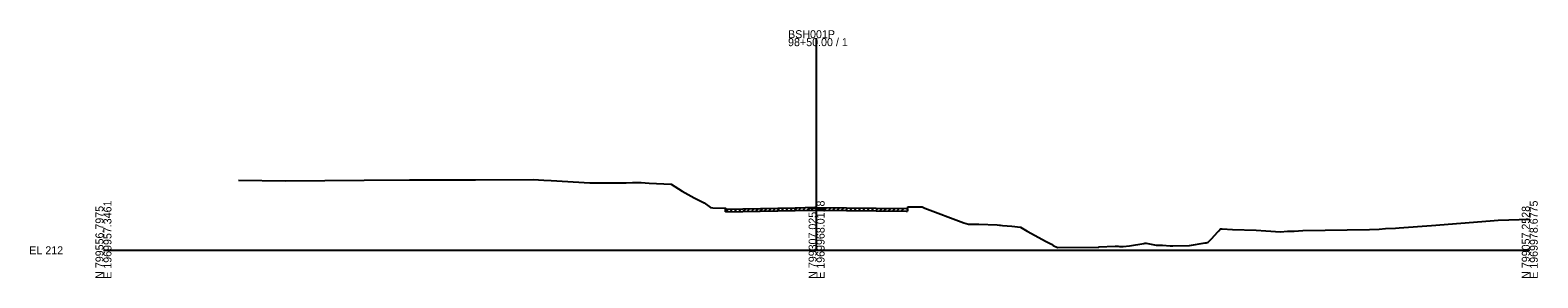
# Model space of a CAD drawing. Extents: x 1979833 to 1982361, y 790388 to 810009.
# Drawn here: x 1981583 to 1982111, y 799888 to 799975 of the extents above; entities that cross this region are included whole.
import ezdxf

# ---------------------------------------------------------------- set-up
doc = ezdxf.new("R2010")
doc.units = 0
for name, color, linetype in [('Default', 7, 'Continuous'), ('RD_GPK_XS_Cell', 7, 'Continuous'), ('RD_XS_ExGround', 7, 'Continuous'), ('RD_XS_ExPaveRet', 7, 'Continuous')]:
    doc.layers.add(name, color=color, linetype=linetype)

msp = doc.modelspace()

# ---------------------------------------------------------------- linework, layer by layer
at = {"layer": 'RD_GPK_XS_Cell'}
for p, q in [((1981858.57, 799897.73), (1981858.57, 799972.27)), ((1981608.57, 799897.73), (1981858.57, 799897.73)), ((1981858.57, 799897.73), (1982108.57, 799897.73))]:
    msp.add_line(p, q, dxfattribs=at)
at = {"layer": 'RD_XS_ExGround'}
msp.add_lwpolyline([(1981655.95, 799922.33), (1981672.36, 799922.18), (1981699.97, 799922.41), (1981715.87, 799922.5), (1981734.9, 799922.49), (1981739.05, 799922.5), (1981759.16, 799922.58), (1981763, 799922.37), (1981765.52, 799922.23), (1981779.02, 799921.48), (1981780.91, 799921.41), (1981791.78, 799921.49), (1981794.04, 799921.51), (1981797.08, 799921.54), (1981799.82, 799921.31), (1981807.58, 799920.92), (1981811.42, 799918.54), (1981815.6, 799916.15), (1981819.2, 799914.38), (1981821.37, 799912.73), (1981822.16, 799912.71), (1981826.59, 799912.51), (1981826.69, 799912.21), (1981851.11, 799912.7), (1981857.92, 799912.84), (1981858.57, 799912.83), (1981889.93, 799912.47), (1981890.49, 799912.47), (1981890.59, 799912.97), (1981895.57, 799912.97), (1981896.51, 799912.57), (1981910.17, 799907.4), (1981911.81, 799906.97), (1981915.43, 799906.89), (1981921.92, 799906.65), (1981922.67, 799906.57), (1981923.04, 799906.54), (1981923.74, 799906.48), (1981927.05, 799906.18), (1981930.06, 799905.83), (1981932.37, 799904.52), (1981939.1, 799900.89), (1981940.87, 799899.84), (1981941.5, 799899.44), (1981943.06, 799898.78), (1981957.51, 799898.89), (1981957.54, 799898.91), (1981963.23, 799899.16), (1981963.8, 799899.2), (1981964.33, 799899.14), (1981964.78, 799899.06), (1981965.31, 799899.05), (1981966.09, 799899.09), (1981968.23, 799899.27), (1981973.23, 799900.16), (1981973.67, 799900.25), (1981974.05, 799900.19), (1981976.97, 799899.65), (1981977.58, 799899.56), (1981978.83, 799899.55), (1981979.88, 799899.56), (1981982.52, 799899.27), (1981983.45, 799899.34), (1981989.24, 799899.4), (1981994.84, 799900.34), (1981995.17, 799900.38), (1981995.83, 799900.58), (1981996.97, 799901.74), (1981999.18, 799904.26), (1981999.58, 799904.56), (1982000.12, 799905.29), (1982000.7, 799905.25), (1982004.4, 799905.08), (1982012.64, 799904.78), (1982016.06, 799904.54), (1982021.18, 799904.25), (1982023.69, 799904.46), (1982024.6, 799904.42), (1982026.02, 799904.51), (1982029.06, 799904.66), (1982052.34, 799905.06), (1982055.8, 799905.22), (1982058.03, 799905.38), (1982061.54, 799905.52), (1982062.8, 799905.58), (1982074.09, 799906.46), (1982094.71, 799908.14), (1982097.44, 799908.3), (1982108.57, 799908.73)], dxfattribs=at)
at = {"layer": 'RD_XS_ExPaveRet'}
for p, q in [((1981826.69, 799911.21), (1981827.71, 799912.23)), ((1981826.69, 799911.21), (1981826.69, 799912.21)), ((1981826.69, 799911.21), (1981851.11, 799911.7)), ((1981828.19, 799911.24), (1981829.21, 799912.26)), ((1981829.69, 799911.27), (1981830.71, 799912.29)), ((1981831.19, 799911.3), (1981832.21, 799912.32)), ((1981832.69, 799911.33), (1981833.71, 799912.35)), ((1981834.19, 799911.36), (1981835.21, 799912.38)), ((1981835.69, 799911.39), (1981836.71, 799912.41)), ((1981837.19, 799911.42), (1981838.21, 799912.44)), ((1981838.69, 799911.45), (1981839.71, 799912.47)), ((1981840.19, 799911.48), (1981841.21, 799912.5)), ((1981841.69, 799911.51), (1981842.71, 799912.53)), ((1981843.19, 799911.54), (1981844.21, 799912.56)), ((1981844.69, 799911.57), (1981845.71, 799912.59)), ((1981846.19, 799911.6), (1981847.21, 799912.62)), ((1981847.69, 799911.63), (1981848.71, 799912.66)), ((1981849.19, 799911.66), (1981850.21, 799912.69)), ((1981850.69, 799911.69), (1981851.71, 799912.71)), ((1981851.11, 799911.7), (1981857.92, 799911.84)), ((1981852.19, 799911.72), (1981853.21, 799912.74)), ((1981853.69, 799911.75), (1981854.71, 799912.77)), ((1981855.19, 799911.78), (1981856.21, 799912.8)), ((1981856.69, 799911.81), (1981857.71, 799912.83)), ((1981857.92, 799911.84), (1981858.57, 799911.83)), ((1981858.19, 799911.83), (1981859.18, 799912.82)), ((1981858.57, 799911.83), (1981889.93, 799911.47)), ((1981859.69, 799911.82), (1981860.68, 799912.8)), ((1981861.19, 799911.8), (1981862.18, 799912.79)), ((1981862.69, 799911.78), (1981863.68, 799912.77)), ((1981864.19, 799911.76), (1981865.18, 799912.75)), ((1981865.69, 799911.75), (1981866.68, 799912.74)), ((1981867.19, 799911.73), (1981868.18, 799912.72)), ((1981868.69, 799911.71), (1981869.68, 799912.7)), ((1981870.19, 799911.7), (1981871.18, 799912.68)), ((1981871.69, 799911.68), (1981872.68, 799912.67)), ((1981873.19, 799911.66), (1981874.18, 799912.65)), ((1981874.69, 799911.64), (1981875.68, 799912.63)), ((1981876.19, 799911.63), (1981877.18, 799912.62)), ((1981877.69, 799911.61), (1981878.68, 799912.6)), ((1981879.19, 799911.59), (1981880.18, 799912.58)), ((1981880.69, 799911.58), (1981881.68, 799912.57)), ((1981882.19, 799911.56), (1981883.18, 799912.55)), ((1981883.69, 799911.54), (1981884.68, 799912.53)), ((1981885.19, 799911.53), (1981886.18, 799912.51)), ((1981886.69, 799911.51), (1981887.68, 799912.5)), ((1981888.19, 799911.49), (1981889.18, 799912.48)), ((1981889.93, 799911.47), (1981890.49, 799911.47)), ((1981890.49, 799912.47), (1981890.49, 799911.47))]:
    msp.add_line(p, q, dxfattribs=at)

# ---------------------------------------------------------------- texts
at = {"layer": 'Default'}
msp.add_text('-', height=0.0001, dxfattribs=at).set_placement((1981608.57, 799897.73))
at = {"layer": 'RD_GPK_XS_Cell'}
for s, p in [('98+50.00 / 1', (1981848.57, 799969.47)), ('BSH001P', (1981848.57, 799972.27)), ('EL 212', (1981582.57, 799896.33))]:
    msp.add_text(s, height=2.8, dxfattribs=at).set_placement(p)
for s, p in [('N 799556.7975', (1981608.57, 799887.73)), ('E 1969957.3461', (1981611.37, 799887.73)), ('N 799307.0251', (1981858.57, 799887.73)), ('E 1969968.0118', (1981861.37, 799887.73)), ('N 799057.2528', (1982108.57, 799887.73)), ('E 1969978.6775', (1982111.37, 799887.73))]:
    msp.add_text(s, height=2.8, rotation=90, dxfattribs=at).set_placement(p)

doc.saveas('drawing.dxf')
